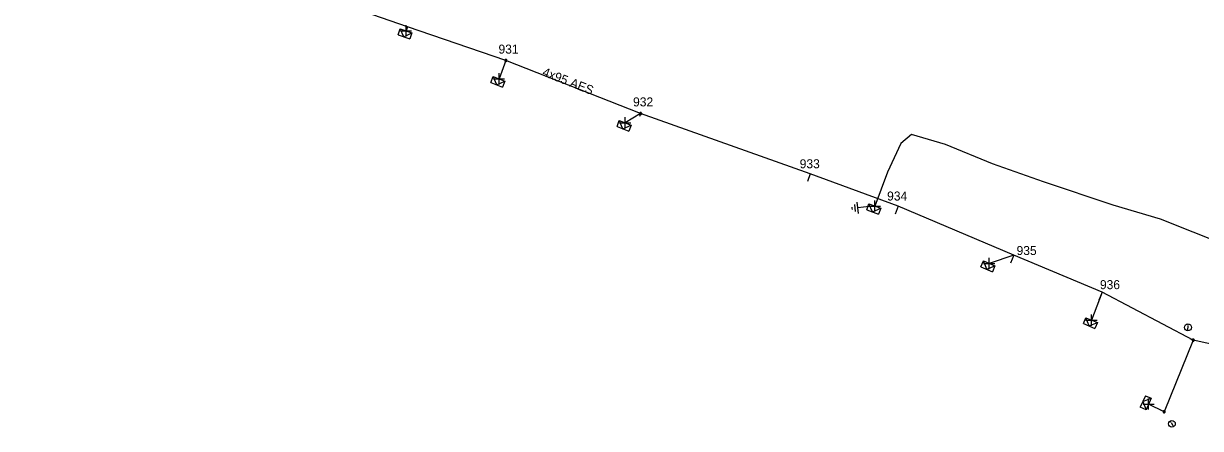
# Model space of a CAD drawing. Extents: x -540466 to -537383, y -1184038 to -1179972.
# Drawn here: x -538474.8 to -538344.1, y -1180287.1 to -1180242.1 of the extents above; entities that cross this region are included whole.
import ezdxf

# ---------------------------------------------------------------- set-up
doc = ezdxf.new("R2010")
doc.units = 0
for name, color, linetype in [('Vrstva 1', 7, 'Continuous'), ('Vrstva 10', 7, 'Continuous'), ('Vrstva 13', 7, 'Continuous'), ('Vrstva 14', 7, 'Continuous'), ('Vrstva 15', 7, 'Continuous'), ('Vrstva 2', 7, 'Continuous'), ('Vrstva 31', 7, 'Continuous'), ('Vrstva 34', 7, 'Continuous'), ('Vrstva 36', 7, 'Continuous'), ('Vrstva 50', 7, 'Continuous'), ('Vrstva 51', 7, 'Continuous'), ('Vrstva 52', 7, 'Continuous'), ('Vrstva 54', 7, 'Continuous'), ('Vrstva 9', 7, 'Continuous')]:
    doc.layers.add(name, color=color, linetype=linetype)

# ---------------------------------------------------------------- blocks, each defined once
blk = doc.blocks.new('NN770')
at = {"layer": 'Vrstva 10'}
for p, q in [((0, 0.19), (0, 0.26)), ((0, -0.28), (0, 0.11))]:
    blk.add_line(p, q, dxfattribs=at)
blk.add_circle((0, -0.01), 0.375, dxfattribs=at)
blk = doc.blocks.new('NN800')
at = {"layer": 'Vrstva 1'}
for points in [[(-0.44, 0.44), (0.44, -0.44)], [(-0.44, -0.44), (0.44, 0.44)]]:
    blk.add_lwpolyline(points, dxfattribs=at)
blk = doc.blocks.new('NN630')
at = {"layer": 'Vrstva 9'}
for points in [[(0, -0.7), (-0.7, 0)], [(-0.7, -0.7), (-0.7, 0), (0.7, 0), (0.7, -0.7)], [(-0.7, -0.7), (0.7, -0.7)], [(0, -0.7), (0.7, 0)]]:
    blk.add_lwpolyline(points, dxfattribs=at)
blk = doc.blocks.new('NN810')
at = {"layer": 'Vrstva 14'}
for points in [[(0, -0.64), (0, -1.89)], [(0.63, -1.89), (-0.62, -1.89)], [(0.39, -2.2), (-0.4, -2.2)], [(0, -2.52), (-0.12, -2.52)], [(0.14, -2.52), (0, -2.52)]]:
    blk.add_lwpolyline(points, dxfattribs=at)
blk = doc.blocks.new('NN500')
at = {"layer": 'Vrstva 2'}
for points in [[(0, -0.24), (0.02, -0.23), (0.05, -0.23), (0.07, -0.22), (0.09, -0.22), (0.12, -0.2), (0.14, -0.19), (0.16, -0.18), (0.17, -0.16), (0.19, -0.14), (0.2, -0.12), (0.21, -0.1), (0.22, -0.07), (0.23, -0.05), (0.23, -0.02), (0.23, 0), (0.23, 0.02), (0.23, 0.05), (0.22, 0.07), (0.21, 0.1), (0.2, 0.12), (0.19, 0.14), (0.17, 0.16), (0.16, 0.17), (0.14, 0.19), (0.12, 0.2), (0.09, 0.21), (0.07, 0.22), (0.05, 0.23), (0.02, 0.23), (0, 0.23), (-0.03, 0.23), (-0.05, 0.23), (-0.07, 0.22), (-0.1, 0.21), (-0.12, 0.2), (-0.14, 0.19), (-0.16, 0.17), (-0.18, 0.16), (-0.19, 0.14), (-0.2, 0.12), (-0.22, 0.1), (-0.22, 0.07), (-0.23, 0.05), (-0.23, 0.02), (-0.24, 0), (-0.23, -0.02), (-0.23, -0.05), (-0.22, -0.07), (-0.22, -0.1), (-0.2, -0.12), (-0.19, -0.14), (-0.18, -0.16), (-0.16, -0.18), (-0.14, -0.19), (-0.12, -0.2), (-0.1, -0.22), (-0.07, -0.22), (-0.05, -0.23), (-0.03, -0.23), (0, -0.24)], [(0, -0.24), (0.02, -0.23), (0.05, -0.23), (0.07, -0.22), (0.09, -0.22), (0.12, -0.2), (0.14, -0.19), (0.16, -0.18), (0.17, -0.16), (0.19, -0.14), (0.2, -0.12), (0.21, -0.1), (0.22, -0.07), (0.23, -0.05), (0.23, -0.02), (0.23, 0), (0.23, 0.02), (0.23, 0.05), (0.22, 0.07), (0.21, 0.1), (0.2, 0.12), (0.19, 0.14), (0.17, 0.16), (0.16, 0.17), (0.14, 0.19), (0.12, 0.2), (0.09, 0.21), (0.07, 0.22), (0.05, 0.23), (0.02, 0.23), (0, 0.23), (-0.03, 0.23), (-0.05, 0.23), (-0.07, 0.22), (-0.1, 0.21), (-0.12, 0.2), (-0.14, 0.19), (-0.16, 0.17), (-0.18, 0.16), (-0.19, 0.14), (-0.2, 0.12), (-0.22, 0.1), (-0.22, 0.07), (-0.23, 0.05), (-0.23, 0.02), (-0.24, 0), (-0.23, -0.02), (-0.23, -0.05), (-0.22, -0.07), (-0.22, -0.1), (-0.2, -0.12), (-0.19, -0.14), (-0.18, -0.16), (-0.16, -0.18), (-0.14, -0.19), (-0.12, -0.2), (-0.1, -0.22), (-0.07, -0.22), (-0.05, -0.23), (-0.03, -0.23), (0, -0.24)], [(0, -0.21), (0.02, -0.2), (0.04, -0.2), (0.06, -0.2), (0.08, -0.19), (0.1, -0.18), (0.12, -0.17), (0.14, -0.15), (0.15, -0.14), (0.16, -0.12), (0.18, -0.1), (0.19, -0.08), (0.19, -0.06), (0.2, -0.04), (0.2, -0.02), (0.2, 0), (0.2, 0.02), (0.2, 0.04), (0.19, 0.06), (0.19, 0.08), (0.18, 0.1), (0.16, 0.12), (0.15, 0.14), (0.14, 0.15), (0.12, 0.17), (0.1, 0.18), (0.08, 0.19), (0.06, 0.19), (0.04, 0.2), (0.02, 0.2), (0, 0.2), (-0.02, 0.2), (-0.04, 0.2), (-0.06, 0.19), (-0.08, 0.19), (-0.1, 0.18), (-0.12, 0.17), (-0.14, 0.15), (-0.15, 0.14), (-0.17, 0.12), (-0.18, 0.1), (-0.19, 0.08), (-0.2, 0.06), (-0.2, 0.04), (-0.21, 0.02), (-0.21, 0), (-0.21, -0.02), (-0.2, -0.04), (-0.2, -0.06), (-0.19, -0.08), (-0.18, -0.1), (-0.17, -0.12), (-0.15, -0.14), (-0.14, -0.15), (-0.12, -0.17), (-0.1, -0.18), (-0.08, -0.19), (-0.06, -0.2), (-0.04, -0.2), (-0.02, -0.2), (0, -0.21)], [(0, -0.18), (0.02, -0.18), (0.04, -0.17), (0.05, -0.17), (0.07, -0.16), (0.09, -0.15), (0.1, -0.14), (0.12, -0.13), (0.13, -0.12), (0.14, -0.1), (0.15, -0.09), (0.16, -0.07), (0.17, -0.05), (0.17, -0.04), (0.17, -0.02), (0.17, 0), (0.17, 0.02), (0.17, 0.04), (0.17, 0.05), (0.16, 0.07), (0.15, 0.09), (0.14, 0.1), (0.13, 0.12), (0.12, 0.13), (0.1, 0.14), (0.09, 0.15), (0.07, 0.16), (0.05, 0.17), (0.04, 0.17), (0.02, 0.17), (0, 0.18), (-0.02, 0.17), (-0.04, 0.17), (-0.06, 0.17), (-0.07, 0.16), (-0.09, 0.15), (-0.1, 0.14), (-0.12, 0.13), (-0.13, 0.12), (-0.14, 0.1), (-0.15, 0.09), (-0.16, 0.07), (-0.17, 0.05), (-0.17, 0.04), (-0.18, 0.02), (-0.18, 0), (-0.18, -0.02), (-0.17, -0.04), (-0.17, -0.05), (-0.16, -0.07), (-0.15, -0.09), (-0.14, -0.1), (-0.13, -0.12), (-0.12, -0.13), (-0.1, -0.14), (-0.09, -0.15), (-0.07, -0.16), (-0.06, -0.17), (-0.04, -0.17), (-0.02, -0.18), (0, -0.18)], [(0, -0.15), (0.01, -0.15), (0.03, -0.14), (0.04, -0.14), (0.06, -0.13), (0.07, -0.13), (0.08, -0.12), (0.1, -0.11), (0.11, -0.1), (0.12, -0.09), (0.13, -0.07), (0.13, -0.06), (0.14, -0.05), (0.14, -0.03), (0.14, -0.02), (0.14, 0), (0.14, 0.01), (0.14, 0.03), (0.14, 0.04), (0.13, 0.06), (0.13, 0.07), (0.12, 0.09), (0.11, 0.1), (0.1, 0.11), (0.08, 0.12), (0.07, 0.13), (0.06, 0.13), (0.04, 0.14), (0.03, 0.14), (0.01, 0.14), (0, 0.15), (-0.02, 0.14), (-0.03, 0.14), (-0.05, 0.14), (-0.06, 0.13), (-0.07, 0.13), (-0.09, 0.12), (-0.1, 0.11), (-0.11, 0.1), (-0.12, 0.09), (-0.13, 0.07), (-0.13, 0.06), (-0.14, 0.04), (-0.14, 0.03), (-0.15, 0.01), (-0.15, 0), (-0.15, -0.02), (-0.14, -0.03), (-0.14, -0.05), (-0.13, -0.06), (-0.13, -0.07), (-0.12, -0.09), (-0.11, -0.1), (-0.1, -0.11), (-0.09, -0.12), (-0.07, -0.13), (-0.06, -0.13), (-0.05, -0.14), (-0.03, -0.14), (-0.02, -0.15), (0, -0.15)], [(0, -0.12), (0.01, -0.12), (0.02, -0.11), (0.03, -0.11), (0.05, -0.11), (0.06, -0.1), (0.07, -0.09), (0.08, -0.09), (0.09, -0.08), (0.09, -0.07), (0.1, -0.06), (0.11, -0.05), (0.11, -0.04), (0.11, -0.02), (0.11, -0.01), (0.12, 0), (0.11, 0.01), (0.11, 0.02), (0.11, 0.04), (0.11, 0.05), (0.1, 0.06), (0.09, 0.07), (0.09, 0.08), (0.08, 0.09), (0.07, 0.09), (0.06, 0.1), (0.05, 0.11), (0.03, 0.11), (0.02, 0.11), (0.01, 0.12), (0, 0.12), (-0.01, 0.12), (-0.03, 0.11), (-0.04, 0.11), (-0.05, 0.11), (-0.06, 0.1), (-0.07, 0.09), (-0.08, 0.09), (-0.09, 0.08), (-0.1, 0.07), (-0.1, 0.06), (-0.11, 0.05), (-0.11, 0.04), (-0.12, 0.02), (-0.12, 0.01), (-0.12, 0), (-0.12, -0.01), (-0.12, -0.02), (-0.11, -0.04), (-0.11, -0.05), (-0.1, -0.06), (-0.1, -0.07), (-0.09, -0.08), (-0.08, -0.09), (-0.07, -0.09), (-0.06, -0.1), (-0.05, -0.11), (-0.04, -0.11), (-0.03, -0.11), (-0.01, -0.12), (0, -0.12)], [(0, -0.09), (0.01, -0.09), (0.02, -0.09), (0.03, -0.08), (0.03, -0.08), (0.04, -0.08), (0.05, -0.07), (0.06, -0.07), (0.06, -0.06), (0.07, -0.05), (0.07, -0.04), (0.08, -0.04), (0.08, -0.03), (0.08, -0.02), (0.09, -0.01), (0.09, 0), (0.09, 0.01), (0.08, 0.02), (0.08, 0.03), (0.08, 0.03), (0.07, 0.04), (0.07, 0.05), (0.06, 0.06), (0.06, 0.06), (0.05, 0.07), (0.04, 0.07), (0.03, 0.08), (0.03, 0.08), (0.02, 0.08), (0.01, 0.09), (0, 0.09), (-0.01, 0.09), (-0.02, 0.08), (-0.03, 0.08), (-0.04, 0.08), (-0.04, 0.07), (-0.05, 0.07), (-0.06, 0.06), (-0.07, 0.06), (-0.07, 0.05), (-0.08, 0.04), (-0.08, 0.03), (-0.08, 0.03), (-0.09, 0.02), (-0.09, 0.01), (-0.09, 0), (-0.09, -0.01), (-0.09, -0.02), (-0.08, -0.03), (-0.08, -0.04), (-0.08, -0.04), (-0.07, -0.05), (-0.07, -0.06), (-0.06, -0.07), (-0.05, -0.07), (-0.04, -0.08), (-0.04, -0.08), (-0.03, -0.08), (-0.02, -0.09), (-0.01, -0.09), (0, -0.09)], [(0, -0.06), (0, -0.06), (0.01, -0.06), (0.02, -0.05), (0.02, -0.05), (0.03, -0.05), (0.03, -0.05), (0.04, -0.04), (0.04, -0.04), (0.05, -0.03), (0.05, -0.03), (0.05, -0.02), (0.05, -0.02), (0.05, -0.01), (0.06, -0.01), (0.06, 0), (0.06, 0.01), (0.05, 0.01), (0.05, 0.02), (0.05, 0.02), (0.05, 0.03), (0.05, 0.03), (0.04, 0.04), (0.04, 0.04), (0.03, 0.05), (0.03, 0.05), (0.02, 0.05), (0.02, 0.05), (0.01, 0.06), (0, 0.06), (0, 0.06), (-0.01, 0.06), (-0.01, 0.06), (-0.02, 0.05), (-0.02, 0.05), (-0.03, 0.05), (-0.03, 0.05), (-0.04, 0.04), (-0.04, 0.04), (-0.05, 0.03), (-0.05, 0.03), (-0.05, 0.02), (-0.06, 0.02), (-0.06, 0.01), (-0.06, 0.01), (-0.06, 0), (-0.06, -0.01), (-0.06, -0.01), (-0.06, -0.02), (-0.05, -0.02), (-0.05, -0.03), (-0.05, -0.03), (-0.04, -0.04), (-0.04, -0.04), (-0.03, -0.05), (-0.03, -0.05), (-0.02, -0.05), (-0.02, -0.05), (-0.01, -0.06), (-0.01, -0.06), (0, -0.06)], [(0, -0.03), (0, -0.03), (0, -0.03), (0.01, -0.03), (0.01, -0.03), (0.01, -0.02), (0.02, -0.02), (0.02, -0.02), (0.02, -0.02), (0.02, -0.02), (0.02, -0.01), (0.02, -0.01), (0.03, -0.01), (0.03, -0.01), (0.03, 0), (0.03, 0), (0.03, 0), (0.03, 0.01), (0.03, 0.01), (0.02, 0.01), (0.02, 0.01), (0.02, 0.02), (0.02, 0.02), (0.02, 0.02), (0.02, 0.02), (0.01, 0.02), (0.01, 0.02), (0.01, 0.03), (0, 0.03), (0, 0.03), (0, 0.03), (0, 0.03), (-0.01, 0.03), (-0.01, 0.03), (-0.01, 0.02), (-0.02, 0.02), (-0.02, 0.02), (-0.02, 0.02), (-0.02, 0.02), (-0.02, 0.02), (-0.03, 0.01), (-0.03, 0.01), (-0.03, 0.01), (-0.03, 0.01), (-0.03, 0), (-0.03, 0), (-0.03, 0), (-0.03, -0.01), (-0.03, -0.01), (-0.03, -0.01), (-0.03, -0.01), (-0.02, -0.02), (-0.02, -0.02), (-0.02, -0.02), (-0.02, -0.02), (-0.02, -0.02), (-0.01, -0.03), (-0.01, -0.03), (-0.01, -0.03), (0, -0.03), (0, -0.03)], [(0.23, 0), (0.7, 0)]]:
    blk.add_lwpolyline(points, dxfattribs=at)
blk = doc.blocks.new('NN510')
at = {"layer": 'Vrstva 2'}
blk.add_lwpolyline([(0, 0), (0, 0.94)], dxfattribs=at)

msp = doc.modelspace()

# ---------------------------------------------------------------- linework, layer by layer
at = {"layer": 'Vrstva 50'}
msp.add_lwpolyline([(-538325.17, -1180281.59), (-538325.82, -1180281.45), (-538344.9, -1180277.24), (-538355.02, -1180271.94), (-538364.82, -1180267.82), (-538377.69, -1180262.38), (-538387.43, -1180258.77), (-538406.28, -1180252.09), (-538421.25, -1180246.19), (-538432.17, -1180242.47), (-538436.04, -1180241.15), (-538439.5, -1180240.02), (-538456.67, -1180234.4), (-538478.81, -1180229.51), (-538492.33, -1180226.31), (-538504.96, -1180223.14), (-538517.98, -1180216.17), (-538538.89, -1180209.94), (-538556.04, -1180205.97)], dxfattribs=at)
at = {"layer": 'Vrstva 52'}
msp.add_lwpolyline([(-538341.29, -1180266.69), (-538348.52, -1180263.82), (-538353.79, -1180262.26), (-538361.54, -1180259.68), (-538367.21, -1180257.67), (-538372.43, -1180255.54), (-538376.18, -1180254.41), (-538377.39, -1180255.41), (-538378.85, -1180258.59), (-538380.27, -1180262.36)], dxfattribs=at)
at = {"layer": 'Vrstva 54'}
for points in [[(-538432.17, -1180242.47), (-538432.34, -1180242.92)], [(-538421.25, -1180246.19), (-538422.01, -1180248.24)], [(-538406.28, -1180252.09), (-538408, -1180253.13)], [(-538364.82, -1180267.82), (-538367.56, -1180268.73)], [(-538355.02, -1180271.94), (-538356.19, -1180275.03)], [(-538344.9, -1180277.24), (-538348.13, -1180285.2), (-538349.85, -1180284.34)]]:
    msp.add_lwpolyline(points, dxfattribs=at)

# ---------------------------------------------------------------- block references
at = {"layer": 'Vrstva 13'}
for p, xscale, yscale, rotation in [((-538421.25, -1180246.19), 0.5, 0.5, -111.41899995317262), ((-538406.28, -1180252.09), 0.5, 0.5, -110.90099998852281), ((-538344.9, -1180277.24), 0.49999999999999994, 0.5000000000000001, 158.41876523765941), ((-538348.13, -1180285.2), 0.5, 0.5, 155.7850000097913)]:
    msp.add_blockref('NN500', p, dxfattribs=dict(at, xscale=xscale, yscale=yscale, rotation=rotation))
for p, rotation in [((-538387.43, -1180258.77), 159.46816955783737), ((-538377.69, -1180262.38), 159.46816955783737), ((-538364.82, -1180267.82), 157.56866398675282), ((-538355.02, -1180271.93), 157.5686640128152)]:
    msp.add_blockref('NN510', p, dxfattribs=dict(at, rotation=rotation))
at = {"layer": 'Vrstva 15', "rotation": -84.39224724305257}
msp.add_blockref('NN810', (-538380.27, -1180262.36), dxfattribs=at)
at = {"layer": 'Vrstva 31'}
for p, rotation in [((-538432.34, -1180242.92), -18.990313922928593), ((-538422.01, -1180248.24), -21.4189251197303), ((-538408, -1180253.13), -20.900800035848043), ((-538380.27, -1180262.36), -20.53980841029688), ((-538367.56, -1180268.73), -23.33586386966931), ((-538356.19, -1180275.03), -22.431335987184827), ((-538349.85, -1180284.34), -114.2145582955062)]:
    msp.add_blockref('NN630', p, dxfattribs=dict(at, rotation=rotation))
at = {"layer": 'Vrstva 34'}
for p, rotation in [((-538432.34, -1180242.92), 45), ((-538422.01, -1180248.24), 45), ((-538408, -1180253.13), 45), ((-538380.27, -1180262.36), 44.99999995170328), ((-538367.56, -1180268.73), 45), ((-538356.19, -1180275.03), 44.99999995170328), ((-538349.85, -1180284.34), 45)]:
    msp.add_blockref('NN800', p, dxfattribs=dict(at, rotation=rotation))
at = {"layer": 'Vrstva 36'}
for p, rotation in [((-538345.48, -1180275.82), -2.2906110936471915), ((-538347.27, -1180286.53), 31.759480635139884)]:
    msp.add_blockref('NN770', p, dxfattribs=dict(at, rotation=rotation))

# ---------------------------------------------------------------- texts
at = {"layer": 'Vrstva 14'}
for s, p in [('931', (-538422.07, -1180245.44)), ('932', (-538407.12, -1180251.3)), ('933', (-538388.61, -1180258.17)), ('934', (-538378.9, -1180261.75)), ('935', (-538364.52, -1180267.8)), ('936', (-538355.26, -1180271.59))]:
    msp.add_text(s, height=1, dxfattribs=at).set_placement(p)
at = {"layer": 'Vrstva 51'}
msp.add_text('4x95 AES', height=1, rotation=338.507, dxfattribs=at).set_placement((-538417.28, -1180247.86))

doc.saveas('drawing.dxf')
